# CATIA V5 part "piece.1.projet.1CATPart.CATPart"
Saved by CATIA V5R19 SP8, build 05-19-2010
Part number: piece.1.projet
Bounding box of the stored display mesh (mm): x 0 to 50, y 0 to 100, z -100 to 100
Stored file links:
  F:\piece.1.projet.1CATPart.CATPart
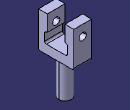
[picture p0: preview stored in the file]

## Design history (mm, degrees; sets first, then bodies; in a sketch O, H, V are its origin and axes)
Parameters
  petitrayon1 = 10 mm
  hauteur1.1 = 100 mm
  hauteur2.1 = 30 mm {= hauteur1.1 *0.3}
  hauteur3.1 = 25 mm {= hauteur1.1 /4}
  hauteur4.1 = 70 mm {= hauteur1.1 *0.7}
  largeur1.1 = 50 mm {= hauteur1.1 /2}
  largeur2.1 = 25 mm
  Longueur1.1 = 100 mm
  Longueur2.1 = 65 mm {= Longueur1.1 *0.65}
  Longueur3.1 = 17.5 mm {= Longueur1.1 *0.175}
  Longueur4.1 = 25 mm {= Longueur1.1 *0.25}
  demiLongueur1 = 50 mm
Body1 (main body)
  Sketch1 on yz-plane, origin (0, 0, 0), H (0, 1, 0), V (0, 0, 1)
    line L1 (0, 0) -> (100, 0)
    line L2 (100, 0) -> (100, 100)
    line L3 (100, 100) -> (75, 100)
    line L4 (0, 100) -> (0, 0)
    line L5 (17.5, 55) -> (17.5, 25)
    line L6 (17.5, 25) -> (82.5, 25)
    line L7 (82.5, 25) -> (82.5, 55)
    line L8 (82.5, 55) -> (75, 55)
    line L9 (75, 55) -> (75, 100)
    line L10 (25, 100) -> (25, 55)
    point P11 (25, 55)
    line L11 (25, 55) -> (17.5, 55)
    line L12 (25, 100) -> (0, 100)
    length L1 = 100 {= Longueur1.1}
    length L4 = 100 {= hauteur1.1}
    length L6 = 65 {= Longueur1.1 *0.65}
    length L7 = 30 {= hauteur2.1}
    distance L6 L1 = 25 {= hauteur3.1}
    distance L5 L4 = 17.5 {= Longueur1.1 *0.175}
    length L12 = 25 {= Longueur4.1}
    length L3 = 25 {= Longueur4.1}
    horizontal: L1 H, L3 H, L6 H, L8 H, L11 H, L12 H
    vertical: L2 V, L4 V, L5 V, L7 V, L9 V, L10 V
    coincidence: P11 L8, L3 L12
  Pad1: profile Sketch1, direction (1, 0, 0), length 50 {= largeur1.1}
  Sketch2 on face of Pad1 from Sketch1.L2, origin (0, 100, 0), H (-1, 0, 0), V (0, 0, 1)
    circle A1 centre (-25, 70) radius 10
    point P1 (-25, 70)
    reference projected line E1 (0, 0) -> (-50, 0) from edge [face of Pad1 from Sketch1.L2 | face of Pad1 from Sketch1.L1]
    reference projected line E2 (-50, 0) -> (-50, 100) from edge [face of Pad1 from Sketch1.L2 | end face of Pad1]
    radius A1 = 10 {= petitrayon1}
    distance P1 E1 = 70 {= hauteur4.1}
    distance E2 P1 = 25 {= largeur1.1 /2}
  Pocket1: profile Sketch2, direction (0, -1, 0), through (limit type 3)
  Fillet1: radius 5, on edge [face of Pad1 from Sketch1.L2 | face of Pad1 from Sketch1.L1]
  Fillet2: radius 5, on edge [face of Pad1 from Sketch1.L1 | face of Pad1 from Sketch1.L4]; edge [face of Pad1 from Sketch1.L6 | face of Pad1 from Sketch1.L7]; edge [face of Pad1 from Sketch1.L5 | face of Pad1 from Sketch1.L6]; edge [face of Pad1 from Sketch1.L11 | face of Pad1 from Sketch1.L5]; edge [face of Pad1 from Sketch1.L7 | face of Pad1 from Sketch1.L8]
  Sketch3 on face of Pad1 from Sketch1.L1, origin (0, 0, 0), H (1, 0, 0), V (0, -1, 0)
    circle A1 centre (25, -50) radius 17.5
    point P1 (25, -50)
    reference projected line E1 (0, 0) -> (0, -100) from edge [start face of Pad1 | face of Pad1 from Sketch1.L1]
    reference projected line E2 (0, 0) -> (50, 0) from edge [face of Fillet2 | face of Pad1 from Sketch1.L4]
    radius A1 = 17.5
    distance P1 E1 = 25
    distance P1 E2 = 50 {= Longueur1.1 /2}
  Pad2: profile Sketch3, direction (0, 0, -1), length 100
